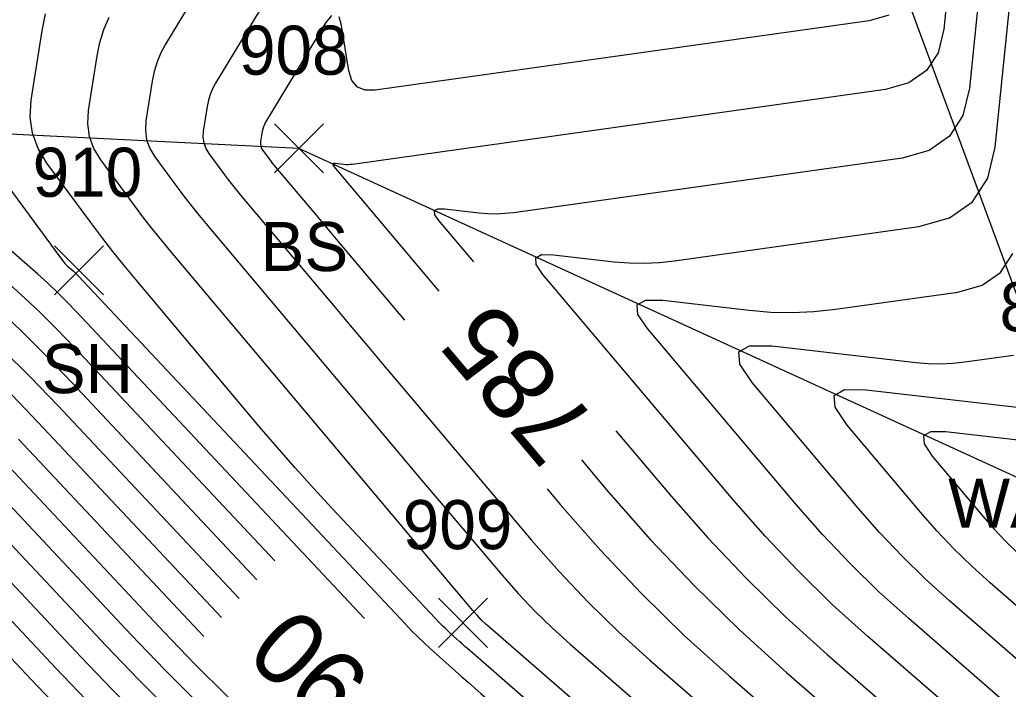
# Model space of a CAD drawing. Extents: x 1650836 to 1652450, y 332578 to 333908.
# Drawn here: x 1652115.54 to 1652155.83, y 332841.97 to 332869.24 of the extents above; entities that cross this region are included whole.
import ezdxf

# ---------------------------------------------------------------- set-up
doc = ezdxf.new("R2010")
doc.units = 0
for name, color, linetype in [('L_A', 7, 'Continuous'), ('L_I', 7, 'Continuous'), ('L_TIC', 7, 'Continuous'), ('LELB', 7, 'Continuous'), ('LSOGCMA', 7, 'Continuous'), ('LSOGCMA_T', 7, 'Continuous'), ('LSOGCMI', 7, 'Continuous'), ('LWS', 7, 'Continuous')]:
    doc.layers.add(name, color=color, linetype=linetype)

msp = doc.modelspace()

# ---------------------------------------------------------------- linework, layer by layer
at = {"layer": 'L_TIC'}
for points in [[(1652125.92, 332863), (1652127.92, 332865)], [(1652127.92, 332863), (1652125.92, 332865)], [(1652116.952, 332858.027), (1652118.952, 332860.027)], [(1652118.952, 332858.027), (1652116.952, 332860.027)], [(1652132.605, 332843.67), (1652134.605, 332845.67)], [(1652134.605, 332843.67), (1652132.605, 332845.67)]]:
    msp.add_lwpolyline(points, dxfattribs=at)
at = {"layer": 'LELB'}
msp.add_lwpolyline([(1652160.434, 332848.646), (1652126.92, 332864), (1652105.537, 332865.052), (1652073.625, 332867.883), (1652056.204, 332873.287), (1652030.254, 332870.914), (1652021.416, 332869.633), (1652021.327, 332871.103)], dxfattribs=at)
at = {"layer": 'LSOGCMA'}
for points in [[(1652156, 332875.697), (1652155.052, 332875.4), (1652154.343, 332874.88), (1652153.874, 332874.136), (1652153.643, 332873.17), (1652153.2, 332868.859), (1652152.969, 332867.897), (1652152.497, 332867.167), (1652151.785, 332866.668), (1652150.832, 332866.402), (1652129.106, 332863.345), (1652129.018, 332863.336), (1652128.93, 332863.332), (1652128.842, 332863.334), (1652128.754, 332863.341), (1652128.402, 332863.382), (1652128.332, 332863.382), (1652128.298, 332863.363), (1652128.301, 332863.324), (1652128.34, 332863.266), (1652132.629, 332858.188)], [(1652124.488, 332845.657), (1652117.098, 332853.523), (1652115.985, 332854.68), (1652114.844, 332855.809)], [(1652138.436, 332851.313), (1652139.545, 332850), (1652141.25, 332848.058), (1652143.027, 332846.185), (1652144.875, 332844.383), (1652146.793, 332842.65), (1652157.507, 332833.342)]]:
    msp.add_lwpolyline(points, dxfattribs=at)
at = {"layer": 'LSOGCMI'}
for points in [[(1652128.971, 332880.609), (1652121.487, 332868.247), (1652121.294, 332867.89), (1652121.138, 332867.52), (1652121.019, 332867.136), (1652120.938, 332866.738), (1652120.687, 332865.122), (1652120.663, 332864.727), (1652120.715, 332864.351), (1652120.844, 332863.994), (1652121.049, 332863.656), (1652122.073, 332862.272), (1652122.328, 332861.934), (1652122.587, 332861.6), (1652122.852, 332861.27), (1652123.122, 332860.944), (1652130.088, 332852.666), (1652130.726, 332851.908), (1652131.364, 332851.151), (1652132.003, 332850.393), (1652132.642, 332849.636), (1652135.199, 332846.609), (1652135.851, 332845.866), (1652136.531, 332845.149), (1652137.238, 332844.46), (1652137.973, 332843.797), (1652157.487, 332826.843)], [(1652129.673, 332876.811), (1652123.524, 332866.654), (1652123.403, 332866.431), (1652123.306, 332866.2), (1652123.232, 332865.96), (1652123.181, 332865.712), (1652123.024, 332864.701), (1652123.009, 332864.454), (1652123.042, 332864.219), (1652123.122, 332863.996), (1652123.25, 332863.785), (1652123.891, 332862.92), (1652124.05, 332862.709), (1652124.212, 332862.5), (1652124.377, 332862.294), (1652124.546, 332862.09), (1652128.324, 332857.6), (1652129.011, 332856.785), (1652129.698, 332855.969), (1652130.385, 332855.154), (1652131.073, 332854.34), (1652136.384, 332848.051), (1652137.522, 332846.755), (1652138.708, 332845.506), (1652139.941, 332844.303), (1652141.221, 332843.147), (1652157.494, 332829.01)], [(1652156.333, 332874.026), (1652155.549, 332873.451), (1652155.03, 332872.628), (1652154.775, 332871.559), (1652154.25, 332866.454), (1652153.982, 332865.339), (1652153.436, 332864.494), (1652152.611, 332863.916), (1652151.508, 332863.607), (1652135.668, 332861.379), (1652135.317, 332861.341), (1652134.965, 332861.325), (1652134.613, 332861.332), (1652134.261, 332861.362), (1652132.851, 332861.524), (1652132.571, 332861.526), (1652132.437, 332861.45), (1652132.448, 332861.296), (1652132.604, 332861.064), (1652134.032, 332859.373)], [(1652157.521, 332837.675), (1652150.114, 332844.11), (1652148.662, 332845.421), (1652147.265, 332846.784), (1652145.92, 332848.201), (1652144.63, 332849.671), (1652136.868, 332858.861), (1652136.594, 332859.267), (1652136.575, 332859.537), (1652136.811, 332859.67), (1652137.3, 332859.667), (1652139.767, 332859.382), (1652140.384, 332859.331), (1652141, 332859.319), (1652141.616, 332859.346), (1652142.231, 332859.413), (1652152.183, 332860.813), (1652153.437, 332861.164), (1652154.375, 332861.821), (1652154.996, 332862.782), (1652155.3, 332864.048), (1652155.957, 332870.436)], [(1652156.996, 332823.369), (1652133.895, 332843.529), (1652133.792, 332843.62), (1652133.689, 332843.71), (1652133.586, 332843.801), (1652133.484, 332843.893), (1652133.075, 332844.259), (1652132.974, 332844.351), (1652132.875, 332844.446), (1652132.778, 332844.543), (1652132.683, 332844.641), (1652128.277, 332849.331), (1652127.517, 332850.151), (1652126.769, 332850.981), (1652126.032, 332851.821), (1652125.306, 332852.672), (1652120.274, 332858.652), (1652119.802, 332859.222), (1652119.338, 332859.8), (1652118.884, 332860.384), (1652118.439, 332860.976), (1652116.646, 332863.397), (1652116.287, 332863.989), (1652116.062, 332864.614), (1652115.971, 332865.272), (1652116.013, 332865.962), (1652116.452, 332868.792), (1652116.594, 332869.487)], [(1652157.48, 332824.677), (1652134.724, 332844.446), (1652134.536, 332844.616), (1652134.355, 332844.793), (1652134.181, 332844.977), (1652134.013, 332845.167), (1652133.358, 332845.943), (1652133.194, 332846.138), (1652133.03, 332846.332), (1652132.867, 332846.526), (1652132.703, 332846.72), (1652121.698, 332859.798), (1652121.327, 332860.246), (1652120.963, 332860.7), (1652120.606, 332861.159), (1652120.256, 332861.624), (1652118.847, 332863.526), (1652118.565, 332863.991), (1652118.388, 332864.482), (1652118.317, 332864.999), (1652118.35, 332865.542), (1652118.695, 332867.765), (1652118.807, 332868.312), (1652118.97, 332868.839), (1652119.184, 332869.349)], [(1652128.242, 332869.417), (1652128.021, 332869.125), (1652125.561, 332865.062), (1652125.513, 332864.973), (1652125.474, 332864.88), (1652125.444, 332864.784), (1652125.424, 332864.685), (1652125.361, 332864.281), (1652125.355, 332864.182), (1652125.368, 332864.088), (1652125.4, 332863.999), (1652125.452, 332863.914), (1652125.708, 332863.568), (1652125.771, 332863.484), (1652125.836, 332863.4), (1652125.903, 332863.318), (1652125.97, 332863.236), (1652127.482, 332861.44), (1652127.756, 332861.114), (1652128.031, 332860.787), (1652128.306, 332860.461), (1652128.581, 332860.135), (1652131.226, 332857.004)], [(1652150.959, 332869.42), (1652150.157, 332869.196), (1652130.035, 332866.365), (1652129.62, 332866.366), (1652129.303, 332866.498), (1652129.082, 332866.762), (1652128.958, 332867.157), (1652128.656, 332869.002), (1652128.56, 332869.356)], [(1652114.402, 332863.325), (1652117.289, 332859.427), (1652117.335, 332859.367), (1652117.385, 332859.31), (1652117.437, 332859.256), (1652117.493, 332859.205), (1652117.721, 332859.005), (1652117.777, 332858.954), (1652117.832, 332858.902), (1652117.886, 332858.849), (1652117.939, 332858.795), (1652131.276, 332844.598), (1652131.516, 332844.348), (1652131.761, 332844.103), (1652132.011, 332843.864), (1652132.267, 332843.63), (1652133.3, 332842.706), (1652133.558, 332842.476), (1652133.818, 332842.246), (1652134.078, 332842.017), (1652134.338, 332841.788), (1652156.104, 332822.793)], [(1652129.592, 332844.849), (1652117.854, 332857.344), (1652117.473, 332857.74), (1652117.082, 332858.126), (1652116.683, 332858.503), (1652116.274, 332858.87), (1652114.62, 332860.32)], [(1652157.527, 332839.841), (1652151.774, 332844.84), (1652150.556, 332845.939), (1652149.383, 332847.084), (1652148.255, 332848.273), (1652147.173, 332849.506), (1652141.132, 332856.658), (1652140.741, 332857.238), (1652140.714, 332857.624), (1652141.05, 332857.814), (1652141.749, 332857.81), (1652145.274, 332857.403), (1652146.155, 332857.33), (1652147.035, 332857.312), (1652147.914, 332857.351), (1652148.793, 332857.447), (1652153.776, 332858.148), (1652154.774, 332858.427), (1652155.519, 332858.949), (1652156.013, 332859.714)], [(1652125.937, 332847.198), (1652117.769, 332855.893), (1652117.059, 332856.63), (1652116.332, 332857.349), (1652115.588, 332858.051), (1652114.827, 332858.735)], [(1652114.494, 332857.6), (1652115.582, 332856.573), (1652116.646, 332855.52), (1652117.684, 332854.441), (1652125.212, 332846.428)], [(1652157.534, 332842.008), (1652153.435, 332845.569), (1652152.45, 332846.458), (1652151.502, 332847.383), (1652150.59, 332848.344), (1652149.715, 332849.341), (1652145.395, 332854.455), (1652144.887, 332855.21), (1652144.852, 332855.711), (1652145.289, 332855.958), (1652146.198, 332855.953), (1652152.077, 332855.274), (1652152.574, 332855.233), (1652153.071, 332855.223), (1652153.567, 332855.245), (1652154.063, 332855.299), (1652156.046, 332855.578)], [(1652123.764, 332844.887), (1652116.295, 332852.837), (1652115.217, 332853.957)], [(1652158.154, 332843.641), (1652155.095, 332846.299), (1652154.344, 332846.977), (1652153.621, 332847.683), (1652152.925, 332848.416), (1652152.258, 332849.176), (1652149.262, 332852.723), (1652148.772, 332853.45), (1652148.738, 332853.933), (1652149.159, 332854.172), (1652150.036, 332854.166), (1652157.847, 332853.265)], [(1652139.839, 332852.497), (1652142.087, 332849.836), (1652143.585, 332848.129), (1652145.146, 332846.485), (1652146.768, 332844.902), (1652148.454, 332843.38), (1652157.514, 332835.509)], [(1652157.88, 332851.917), (1652153.27, 332852.449), (1652152.666, 332852.453), (1652152.375, 332852.289), (1652152.399, 332851.956), (1652152.736, 332851.455), (1652154.8, 332849.011), (1652155.26, 332848.487), (1652155.74, 332847.982), (1652156.238, 332847.496)], [(1652115.493, 332852.15), (1652122.835, 332844.334), (1652123.042, 332844.119)], [(1652114.69, 332851.463), (1652121.428, 332844.29), (1652122.682, 332842.984), (1652123.964, 332841.705), (1652125.273, 332840.455), (1652126.61, 332839.233), (1652132.011, 332834.4), (1652133.363, 332833.194), (1652134.719, 332831.992), (1652136.079, 332830.795), (1652137.442, 332829.601), (1652149.86, 332818.764), (1652150.175, 332818.501), (1652150.5, 332818.253), (1652150.835, 332818.018), (1652151.181, 332817.798), (1652152.587, 332816.948), (1652152.941, 332816.781), (1652153.303, 332816.707), (1652153.672, 332816.726), (1652154.047, 332816.838), (1652157.508, 332818.281)], [(1652156.715, 332817.316), (1652153.646, 332816.037), (1652153.226, 332815.912), (1652152.814, 332815.891), (1652152.41, 332815.973), (1652152.014, 332816.159), (1652150.444, 332817.11), (1652150.058, 332817.355), (1652149.683, 332817.617), (1652149.32, 332817.895), (1652148.968, 332818.188), (1652137.886, 332827.86), (1652136.365, 332829.192), (1652134.848, 332830.528), (1652133.336, 332831.868), (1652131.827, 332833.214), (1652125.735, 332838.664), (1652124.277, 332839.997), (1652122.849, 332841.361), (1652121.451, 332842.756), (1652120.082, 332844.181), (1652113.887, 332850.776)], [(1652155.922, 332816.352), (1652153.244, 332815.236), (1652152.78, 332815.098), (1652152.325, 332815.075), (1652151.879, 332815.165), (1652151.441, 332815.371), (1652149.707, 332816.421), (1652149.28, 332816.692), (1652148.866, 332816.982), (1652148.464, 332817.288), (1652148.076, 332817.613), (1652138.329, 332826.119), (1652136.651, 332827.588), (1652134.977, 332829.063), (1652133.308, 332830.542), (1652131.643, 332832.027), (1652124.51, 332838.409), (1652123.104, 332839.695), (1652121.727, 332841.01), (1652120.378, 332842.355), (1652119.059, 332843.73), (1652113.084, 332850.089)], [(1652137.034, 332850.128), (1652137.57, 332849.493), (1652139.193, 332847.644), (1652140.884, 332845.862), (1652142.643, 332844.146), (1652144.469, 332842.497), (1652157.5, 332831.176)], [(1652155.918, 332815.432), (1652155.588, 332815.508), (1652155.128, 332815.388), (1652152.842, 332814.435), (1652152.335, 332814.284), (1652151.837, 332814.258), (1652151.348, 332814.358), (1652150.868, 332814.583), (1652148.97, 332815.732), (1652148.502, 332816.03), (1652148.049, 332816.346), (1652147.609, 332816.682), (1652147.184, 332817.037), (1652138.327, 332824.767), (1652136.713, 332826.179), (1652135.104, 332827.597), (1652133.5, 332829.019), (1652131.9, 332830.446), (1652123.285, 332838.154), (1652121.931, 332839.392), (1652120.604, 332840.659), (1652119.306, 332841.954), (1652118.035, 332843.278), (1652112.282, 332849.402)], [(1652111.479, 332848.715), (1652117.011, 332842.826), (1652118.233, 332841.553), (1652119.482, 332840.308), (1652120.757, 332839.09), (1652122.06, 332837.899), (1652132.262, 332828.771), (1652133.745, 332827.448), (1652135.232, 332826.13), (1652136.723, 332824.817), (1652138.218, 332823.508), (1652142.625, 332819.662)], [(1652110.676, 332848.028), (1652115.988, 332842.374), (1652117.161, 332841.152), (1652118.36, 332839.956), (1652119.584, 332838.787), (1652120.834, 332837.644), (1652132.624, 332827.096), (1652133.99, 332825.878), (1652135.359, 332824.664), (1652136.732, 332823.454), (1652138.109, 332822.249), (1652139.312, 332821.199)]]:
    msp.add_lwpolyline(points, dxfattribs=at)
at = {"layer": 'LWS'}
msp.add_lwpolyline([(1652157.84, 332853.547), (1652146.567, 332884.053), (1652141.158, 332895.272)], dxfattribs=at)

# ---------------------------------------------------------------- texts
at = {"layer": 'L_A'}
for s, p in [('BS', (1652125.361, 332859)), ('SH', (1652116.44, 332854.027)), ('WALLS', (1652153.383, 332848.547))]:
    msp.add_text(s, height=2, dxfattribs=at).set_placement(p)
at = {"layer": 'L_I'}
for s, p in [('908', (1652124.479, 332867)), ('910', (1652116.07, 332862.027)), ('874', (1652155.478, 332856.547)), ('909', (1652131.156, 332847.67))]:
    msp.add_text(s, height=2, dxfattribs=at).set_placement(p)
at = {"layer": 'LSOGCMA_T'}
for s, rotation, p in [('785', 130.1844, (1652139.148, 332852.795)), ('790', 136.7696, (1652131.613, 332840.89))]:
    msp.add_text(s, height=3, rotation=rotation, dxfattribs=at).set_placement(p)

doc.saveas('drawing.dxf')
